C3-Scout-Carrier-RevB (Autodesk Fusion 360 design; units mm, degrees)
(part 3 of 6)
work_plane "WorkPlane4" AlongDistance -2.4 ExtraOffset 0
sketch "M3 nut outline" plane through (0, 0, -2.4) normal (0, 0, 1) x axis (1, 0, 0)
  line L1 (-10.41, -42.246) -> (-8.82, -45)
  line L2 (-13.59, -42.246) -> (-10.41, -42.246)
  line L3 (-15.18, -45) -> (-13.59, -42.246)
  line L4 (-13.59, -47.754) -> (-15.18, -45)
  line L5 (-10.41, -47.754) -> (-13.59, -47.754)
  line L6 (-8.82, -45) -> (-10.41, -47.754)
extrude "Extrude4" new body sketch "M3 nut outline" along normal blind 2.4
work_plane "WorkPlane5" AlongDistance -2.4 ExtraOffset 0
sketch "Nut thread clearance profile" plane through (0, 0, -2.4) normal (0, 0, 1) x axis (1, 0, 0)
  circle C1 centre (-12, -45) radius 1.55
extrude "Extrude5" cut sketch "Nut thread clearance profile" along normal blind 2.4
work_plane "WorkPlane6" AlongDistance -3.2 ExtraOffset 0
sketch "M3 x8 shank profile (1)" plane through (0, 0, -3.2) normal (0, 0, 1) x axis (1, 0, 0)
  circle C1 centre (12, -45) radius 1.5
extrude "Extrude6" new body sketch "M3 x8 shank profile (1)" along normal blind 8
work_plane "WorkPlane7" AlongDistance 4.8 ExtraOffset 0
sketch "M3 button head profile (1)" plane through (0, 0, 4.8) normal (0, 0, 1) x axis (1, 0, 0)
  circle C1 centre (12, -45) radius 2.7
extrude "Extrude7" new body sketch "M3 button head profile (1)" along normal blind 2.2
work_plane "WorkPlane8" AlongDistance 5.9 ExtraOffset 0
sketch "M3 hex drive (1)" plane through (0, 0, 5.9) normal (0, 0, 1) x axis (1, 0, 0)
  line L1 (12.7, -43.7876) -> (13.4, -45)
  line L2 (11.3, -43.7876) -> (12.7, -43.7876)
  line L3 (10.6, -45) -> (11.3, -43.7876)
  line L4 (11.3, -46.2124) -> (10.6, -45)
  line L5 (12.7, -46.2124) -> (11.3, -46.2124)
  line L6 (13.4, -45) -> (12.7, -46.2124)
extrude "Extrude8" cut sketch "M3 hex drive (1)" along normal blind 1.1
work_plane "WorkPlane9" AlongDistance -2.4 ExtraOffset 0
sketch "M3 nut outline (1)" plane through (0, 0, -2.4) normal (0, 0, 1) x axis (1, 0, 0)
  line L1 (13.59, -42.246) -> (15.18, -45)
  line L2 (10.41, -42.246) -> (13.59, -42.246)
  line L3 (8.82, -45) -> (10.41, -42.246)
  line L4 (10.41, -47.754) -> (8.82, -45)
  line L5 (13.59, -47.754) -> (10.41, -47.754)
  line L6 (15.18, -45) -> (13.59, -47.754)
extrude "Extrude9" new body sketch "M3 nut outline (1)" along normal blind 2.4
work_plane "WorkPlane10" AlongDistance -2.4 ExtraOffset 0
sketch "Nut thread clearance profile (1)" plane through (0, 0, -2.4) normal (0, 0, 1) x axis (1, 0, 0)
  circle C1 centre (12, -45) radius 1.55
extrude "Extrude10" cut sketch "Nut thread clearance profile (1)" along normal blind 2.4
sketch "Clear bumper lower beam profile" plane through (0, 0, 0) normal (0, 0, 1) x axis (1, 0, 0)
  line L1 (18, -52) -> (-18, -52)
  line L2 (18, -49.7) -> (18, -52)
  line L3 (-18, -49.7) -> (18, -49.7)
  line L4 (-18, -52) -> (-18, -49.7)
extrude "Extrude8" cut sketch "Clear bumper lower beam profile" along normal blind 1.8
work_plane "WorkPlane6" AlongDistance 3 ExtraOffset 0
sketch "PCB shoulder clearance behind USB mouth profile" plane through (0, 0, 3) normal (0, 0, 1) x axis (1, 0, 0)
  line L1 (9, -51.3) -> (-9, -51.3)
  line L2 (9, -49.5) -> (9, -51.3)
  line L3 (-9, -49.5) -> (9, -49.5)
  line L4 (-9, -51.3) -> (-9, -49.5)
extrude "Extrude10" cut sketch "PCB shoulder clearance behind USB mouth profile" along normal blind 3.2
work_plane "WorkPlane3" AlongDistance 4.8 ExtraOffset 0
sketch "Leave solder pads accessible profile" plane through (0, 0, 4.8) normal (0, 0, 1) x axis (1, 0, 0)
  line L1 (-4.4, -29.4) -> (-7, -29.4)
  line L2 (-4.4, -26.9) -> (-4.4, -29.4)
  line L3 (-7, -26.9) -> (-4.4, -26.9)
  line L4 (-7, -29.4) -> (-7, -26.9)
extrude "Extrude3" cut sketch "Leave solder pads accessible profile" along normal blind 1.3
work_plane "WorkPlane4" AlongDistance 4.8 ExtraOffset 0
sketch "Leave solder pads accessible profile (1)" plane through (0, 0, 4.8) normal (0, 0, 1) x axis (1, 0, 0)
  line L1 (7, -29.4) -> (4.4, -29.4)
  line L2 (7, -26.9) -> (7, -29.4)
  line L3 (4.4, -26.9) -> (7, -26.9)
  line L4 (4.4, -29.4) -> (4.4, -26.9)
extrude "Extrude4" cut sketch "Leave solder pads accessible profile (1)" along normal blind 1.3
sketch "Chamfered driver carrier outline" plane through (0, 0, 0) normal (0, 0, 1) x axis (1, 0, 0)
  line L1 (12.15, -13.5) -> (-12.15, -13.5)
  line L2 (14.15, -11.5) -> (12.15, -13.5)
  line L3 (14.15, 11.5) -> (14.15, -11.5)
  line L4 (12.15, 13.5) -> (14.15, 11.5)
  line L5 (-12.15, 13.5) -> (12.15, 13.5)
  line L6 (-14.15, 11.5) -> (-12.15, 13.5)
  line L7 (-14.15, -11.5) -> (-14.15, 11.5)
  line L8 (-12.15, -13.5) -> (-14.15, -11.5)
extrude "Extrude1" new body sketch "Chamfered driver carrier outline" along normal blind 1.6
sketch "Driver underside cooling opening profile" plane through (0, 0, 0) normal (0, 0, 1) x axis (1, 0, 0)
  line L1 (5, -3.5) -> (-5, -3.5)
  line L2 (5, 5) -> (5, -3.5)
  line L3 (-5, 5) -> (5, 5)
  line L4 (-5, -3.5) -> (-5, 5)
extrude "Extrude2" cut sketch "Driver underside cooling opening profile" along normal blind 1.6
work_plane "WorkPlane1" AlongDistance 1.6 ExtraOffset 0
sketch "End locating rail profile" plane through (0, 0, 1.6) normal (0, 0, 1) x axis (1, 0, 0)
  line L1 (8, -12.3) -> (-8, -12.3)
  line L2 (8, -10.8) -> (8, -12.3)
  line L3 (-8, -10.8) -> (8, -10.8)
  line L4 (-8, -12.3) -> (-8, -10.8)
extrude "Extrude3" add sketch "End locating rail profile" along normal blind 2.1
work_plane "WorkPlane2" AlongDistance 1.6 ExtraOffset 0
sketch "End locating rail profile (1)" plane through (0, 0, 1.6) normal (0, 0, 1) x axis (1, 0, 0)
  line L1 (8, 10.8) -> (-8, 10.8)
  line L2 (8, 12.3) -> (8, 10.8)
  line L3 (-8, 12.3) -> (8, 12.3)
  line L4 (-8, 10.8) -> (-8, 12.3)
extrude "Extrude4" add sketch "End locating rail profile (1)" along normal blind 2.1
work_plane "WorkPlane3" AlongDistance 1.6 ExtraOffset 0
sketch "Side locating tab profile" plane through (0, 0, 1.6) normal (0, 0, 1) x axis (1, 0, 0)
  line L1 (-12.65, -2) -> (-14.15, -2)
  line L2 (-12.65, 2) -> (-12.65, -2)
  line L3 (-14.15, 2) -> (-12.65, 2)
  line L4 (-14.15, -2) -> (-14.15, 2)
extrude "Extrude5" add sketch "Side locating tab profile" along normal blind 2.1
work_plane "WorkPlane4" AlongDistance 1.6 ExtraOffset 0
sketch "Side locating tab profile (1)" plane through (0, 0, 1.6) normal (0, 0, 1) x axis (1, 0, 0)
  line L1 (14.15, -2) -> (12.65, -2)
  line L2 (14.15, 2) -> (14.15, -2)
  line L3 (12.65, 2) -> (14.15, 2)
  line L4 (12.65, -2) -> (12.65, 2)
extrude "Extrude6" add sketch "Side locating tab profile (1)" along normal blind 2.1
sketch "Cable access profile" plane through (0, 0, 0) normal (0, 0, 1) x axis (1, 0, 0)
  line L1 (-11.5, 4) -> (-13.5, 4)
  line L2 (-11.5, 8) -> (-11.5, 4)
  line L3 (-13.5, 8) -> (-11.5, 8)
  line L4 (-13.5, 4) -> (-13.5, 8)
extrude "Extrude7" cut sketch "Cable access profile" along normal blind 1.6
sketch "Cable access profile (1)" plane through (0, 0, 0) normal (0, 0, 1) x axis (1, 0, 0)
  line L1 (13.5, 4) -> (11.5, 4)
  line L2 (13.5, 8) -> (13.5, 4)
  line L3 (11.5, 8) -> (13.5, 8)
  line L4 (11.5, 4) -> (11.5, 8)
extrude "Extrude8" cut sketch "Cable access profile (1)" along normal blind 1.6
sketch "Red PCB 24.7 x21 provisional profile" plane through (0, 0, 0) normal (0, 0, 1) x axis (1, 0, 0)
  line L1 (12.35, -10.5) -> (-12.35, -10.5)
  line L2 (12.35, 10.5) -> (12.35, -10.5)
  line L3 (-12.35, 10.5) -> (12.35, 10.5)
  line L4 (-12.35, -10.5) -> (-12.35, 10.5)
extrude "Extrude1" new body sketch "Red PCB 24.7 x21 provisional profile" along normal blind 1
sketch "Solder through holes profile" plane through (0, 0, 0) normal (0, 0, 1) x axis (1, 0, 0)
  circle C1 centre (-7.2, -0.3) radius 0.625
  circle C2 centre (-7.2, 2.24) radius 0.625
  circle C3 centre (-7.2, 5.8) radius 0.625
  circle C4 centre (-7.2, 8.34) radius 0.625
  circle C5 centre (7.8, -0.3) radius 0.625
  circle C6 centre (7.8, 2.24) radius 0.625
  circle C7 centre (7.8, 5.8) radius 0.625
  circle C8 centre (7.8, 8.34) radius 0.625
  circle C9 centre (-10.8, -8.8) radius 0.625
  circle C10 centre (-10.8, -5.6) radius 0.625
extrude "Extrude2" cut sketch "Solder through holes profile" along normal blind 1
sketch "Uncommitted mounting hole reference profile" plane through (0, 0, 0) normal (0, 0, 1) x axis (1, 0, 0)
  circle C1 centre (-10.4, -2.5) radius 1.15
extrude "Extrude3" cut sketch "Uncommitted mounting hole reference profile" along normal blind 1
work_plane "WorkPlane1" AlongDistance 1 ExtraOffset 0
sketch "Top solder pads profiles" plane through (0, 0, 1) normal (0, 0, 1) x axis (1, 0, 0)
  circle C1 centre (-7.2, -0.3) radius 1.25
  circle C2 centre (-7.2, -0.3) radius 0.625
  circle C3 centre (-7.2, 2.24) radius 1.25
  circle C4 centre (-7.2, 2.24) radius 0.625
  circle C5 centre (-7.2, 5.8) radius 1.25
  circle C6 centre (-7.2, 5.8) radius 0.625
  circle C7 centre (-7.2, 8.34) radius 1.25
  circle C8 centre (-7.2, 8.34) radius 0.625
  circle C9 centre (7.8, -0.3) radius 1.25
  circle C10 centre (7.8, -0.3) radius 0.625
  circle C11 centre (7.8, 2.24) radius 1.25
  circle C12 centre (7.8, 2.24) radius 0.625
  circle C13 centre (7.8, 5.8) radius 1.25
  circle C14 centre (7.8, 5.8) radius 0.625
  circle C15 centre (7.8, 8.34) radius 1.25
  circle C16 centre (7.8, 8.34) radius 0.625
  circle C17 centre (-10.8, -8.8) radius 1.25
  circle C18 centre (-10.8, -8.8) radius 0.625
  circle C19 centre (-10.8, -5.6) radius 1.25
  circle C20 centre (-10.8, -5.6) radius 0.625
extrude "Extrude4" new body sketch "Top solder pads profiles" along normal blind 0.04
work_plane "WorkPlane2" AlongDistance -0.04 ExtraOffset 0
sketch "Bottom solder pads profiles" plane through (0, 0, -0.04) normal (0, 0, 1) x axis (1, 0, 0)
  circle C1 centre (-7.2, -0.3) radius 1.25
  circle C2 centre (-7.2, -0.3) radius 0.625
  circle C3 centre (-7.2, 2.24) radius 1.25
  circle C4 centre (-7.2, 2.24) radius 0.625
  circle C5 centre (-7.2, 5.8) radius 1.25
  circle C6 centre (-7.2, 5.8) radius 0.625
  circle C7 centre (-7.2, 8.34) radius 1.25
  circle C8 centre (-7.2, 8.34) radius 0.625
  circle C9 centre (7.8, -0.3) radius 1.25
  circle C10 centre (7.8, -0.3) radius 0.625
  circle C11 centre (7.8, 2.24) radius 1.25
  circle C12 centre (7.8, 2.24) radius 0.625
  circle C13 centre (7.8, 5.8) radius 1.25
  circle C14 centre (7.8, 5.8) radius 0.625
  circle C15 centre (7.8, 8.34) radius 1.25
  circle C16 centre (7.8, 8.34) radius 0.625
  circle C17 centre (-10.8, -8.8) radius 1.25
  circle C18 centre (-10.8, -8.8) radius 0.625
  circle C19 centre (-10.8, -5.6) radius 1.25
  circle C20 centre (-10.8, -5.6) radius 0.625
extrude "Extrude5" new body sketch "Bottom solder pads profiles" along normal blind 0.04
work_plane "WorkPlane3" AlongDistance 1.2 ExtraOffset 0
sketch "TC1508A SOP16 body profile" plane through (0, 0, 1.2) normal (0, 0, 1) x axis (1, 0, 0)
  line L1 (1.95, -0.7) -> (-1.95, -0.7)
  line L2 (1.95, 9.2) -> (1.95, -0.7)
  line L3 (-1.95, 9.2) -> (1.95, 9.2)
  line L4 (-1.95, -0.7) -> (-1.95, 9.2)
extrude "Extrude6" new body sketch "TC1508A SOP16 body profile" along normal blind 1.5
work_plane "WorkPlane4" AlongDistance 1.04 ExtraOffset 0
sketch "Sixteen formed IC leads profiles" plane through (0, 0, 1.04) normal (0, 0, 1) x axis (1, 0, 0)
  line L1 (-1.8, -0.405) -> (-3.05, -0.405)
  line L2 (-1.8, 0.015) -> (-1.8, -0.405)
  line L3 (-3.05, 0.015) -> (-1.8, 0.015)
  line L4 (-3.05, -0.405) -> (-3.05, 0.015)
  line L5 (-1.8, 0.865) -> (-3.05, 0.865)
  line L6 (-1.8, 1.285) -> (-1.8, 0.865)
  line L7 (-3.05, 1.285) -> (-1.8, 1.285)
  line L8 (-3.05, 0.865) -> (-3.05, 1.285)
  line L9 (-1.8, 2.135) -> (-3.05, 2.135)
  line L10 (-1.8, 2.555) -> (-1.8, 2.135)
  line L11 (-3.05, 2.555) -> (-1.8, 2.555)
  line L12 (-3.05, 2.135) -> (-3.05, 2.555)
  line L13 (-1.8, 3.405) -> (-3.05, 3.405)
  line L14 (-1.8, 3.825) -> (-1.8, 3.405)
  line L15 (-3.05, 3.825) -> (-1.8, 3.825)
  line L16 (-3.05, 3.405) -> (-3.05, 3.825)
  line L17 (-1.8, 4.675) -> (-3.05, 4.675)
  line L18 (-1.8, 5.095) -> (-1.8, 4.675)
  line L19 (-3.05, 5.095) -> (-1.8, 5.095)
  line L20 (-3.05, 4.675) -> (-3.05, 5.095)
  line L21 (-1.8, 5.945) -> (-3.05, 5.945)
  line L22 (-1.8, 6.365) -> (-1.8, 5.945)
  line L23 (-3.05, 6.365) -> (-1.8, 6.365)
  line L24 (-3.05, 5.945) -> (-3.05, 6.365)
  line L25 (-1.8, 7.215) -> (-3.05, 7.215)
  line L26 (-1.8, 7.635) -> (-1.8, 7.215)
  line L27 (-3.05, 7.635) -> (-1.8, 7.635)
  line L28 (-3.05, 7.215) -> (-3.05, 7.635)
  line L29 (-1.8, 8.485) -> (-3.05, 8.485)
  line L30 (-1.8, 8.905) -> (-1.8, 8.485)
  line L31 (-3.05, 8.905) -> (-1.8, 8.905)
  line L32 (-3.05, 8.485) -> (-3.05, 8.905)
  line L33 (3.05, -0.405) -> (1.8, -0.405)
  line L34 (3.05, 0.015) -> (3.05, -0.405)
  line L35 (1.8, 0.015) -> (3.05, 0.015)
  line L36 (1.8, -0.405) -> (1.8, 0.015)
  line L37 (3.05, 0.865) -> (1.8, 0.865)
  line L38 (3.05, 1.285) -> (3.05, 0.865)
  line L39 (1.8, 1.285) -> (3.05, 1.285)
  line L40 (1.8, 0.865) -> (1.8, 1.285)
  line L41 (3.05, 2.135) -> (1.8, 2.135)
  line L42 (3.05, 2.555) -> (3.05, 2.135)
  line L43 (1.8, 2.555) -> (3.05, 2.555)
  line L44 (1.8, 2.135) -> (1.8, 2.555)
  line L45 (3.05, 3.405) -> (1.8, 3.405)
  line L46 (3.05, 3.825) -> (3.05, 3.405)
  line L47 (1.8, 3.825) -> (3.05, 3.825)
  line L48 (1.8, 3.405) -> (1.8, 3.825)
  line L49 (3.05, 4.675) -> (1.8, 4.675)
  line L50 (3.05, 5.095) -> (3.05, 4.675)
  line L51 (1.8, 5.095) -> (3.05, 5.095)
  line L52 (1.8, 4.675) -> (1.8, 5.095)
  line L53 (3.05, 5.945) -> (1.8, 5.945)
  line L54 (3.05, 6.365) -> (3.05, 5.945)
  line L55 (1.8, 6.365) -> (3.05, 6.365)
  line L56 (1.8, 5.945) -> (1.8, 6.365)
  line L57 (3.05, 7.215) -> (1.8, 7.215)
  line L58 (3.05, 7.635) -> (3.05, 7.215)
  line L59 (1.8, 7.635) -> (3.05, 7.635)
  line L60 (1.8, 7.215) -> (1.8, 7.635)
  line L61 (3.05, 8.485) -> (1.8, 8.485)
  line L62 (3.05, 8.905) -> (3.05, 8.485)
  line L63 (1.8, 8.905) -> (3.05, 8.905)
  line L64 (1.8, 8.485) -> (1.8, 8.905)
extrude "Extrude7" new body sketch "Sixteen formed IC leads profiles" along normal blind 0.43
work_plane "WorkPlane5" AlongDistance 2.55 ExtraOffset 0
sketch "IC orientation dimple profile" plane through (0, 0, 2.55) normal (0, 0, 1) x axis (1, 0, 0)
  circle C1 centre (-1.2, -0.05) radius 0.25
extrude "Extrude8" cut sketch "IC orientation dimple profile" along normal blind 0.15
work_plane "WorkPlane6" AlongDistance 2.7 ExtraOffset 0
sketch "TC1508A marking" plane through (0, 0, 2.7) normal (0, 0, 1) x axis (1, 0, 0)
  dimension "d730" = 0.7
  dimension "d731" = "'TC1508A'"
extrude "Extrude9" new body sketch "TC1508A marking" along normal blind 0.02
work_plane "WorkPlane7" AlongDistance 1 ExtraOffset 0
sketch "Capacitor square foot profile" plane through (0, 0, 1) normal (0, 0, 1) x axis (1, 0, 0)
  line L1 (-0.6, -10) -> (-7.4, -10)
  line L2 (-0.6, -3.2) -> (-0.6, -10)
  line L3 (-7.4, -3.2) -> (-0.6, -3.2)
  line L4 (-7.4, -10) -> (-7.4, -3.2)
extrude "Extrude10" new body sketch "Capacitor square foot profile" along normal blind 1
work_plane "WorkPlane8" AlongDistance 2 ExtraOffset 0
sketch "100uF capacitor aluminum can profile" plane through (0, 0, 2) normal (0, 0, 1) x axis (1, 0, 0)
  circle C1 centre (-4, -6.6) radius 3.15
extrude "Extrude11" new body sketch "100uF capacitor aluminum can profile" along normal blind 4.2
work_plane "WorkPlane9" AlongDistance 6.2 ExtraOffset 0
sketch "Capacitor polarity stripe profile" plane through (0, 0, 6.2) normal (0, 0, 1) x axis (1, 0, 0)
  line L1 (-5.8, -7.2) -> (-6.8, -7.2)
  line L2 (-5.8, -6) -> (-5.8, -7.2)
  line L3 (-6.8, -6) -> (-5.8, -6)
  line L4 (-6.8, -7.2) -> (-6.8, -6)
extrude "Extrude12" new body sketch "Capacitor polarity stripe profile" along normal blind 0.025
work_plane "WorkPlane10" AlongDistance 6.2 ExtraOffset 0
sketch "100 marking" plane through (0, 0, 6.2) normal (0, 0, 1) x axis (1, 0, 0)
  dimension "d748" = 0.85
  dimension "d749" = "'100'"
extrude "Extrude13" new body sketch "100 marking" along normal blind 0.025
work_plane "WorkPlane11" AlongDistance 1 ExtraOffset 0
sketch "Capacitor square foot profile (1)" plane through (0, 0, 1) normal (0, 0, 1) x axis (1, 0, 0)
  line L1 (7, -10) -> (0.2, -10)
  line L2 (7, -3.2) -> (7, -10)
  line L3 (0.2, -3.2) -> (7, -3.2)
  line L4 (0.2, -10) -> (0.2, -3.2)
extrude "Extrude14" new body sketch "Capacitor square foot profile (1)" along normal blind 1
work_plane "WorkPlane12" AlongDistance 2 ExtraOffset 0
sketch "100uF capacitor aluminum can profile (1)" plane through (0, 0, 2) normal (0, 0, 1) x axis (1, 0, 0)
  circle C1 centre (3.6, -6.6) radius 3.15
extrude "Extrude15" new body sketch "100uF capacitor aluminum can profile (1)" along normal blind 4.2
work_plane "WorkPlane13" AlongDistance 6.2 ExtraOffset 0
sketch "Capacitor polarity stripe profile (1)" plane through (0, 0, 6.2) normal (0, 0, 1) x axis (1, 0, 0)
  line L1 (1.8, -7.2) -> (0.8, -7.2)
  line L2 (1.8, -6) -> (1.8, -7.2)
  line L3 (0.8, -6) -> (1.8, -6)
  line L4 (0.8, -7.2) -> (0.8, -6)
extrude "Extrude16" new body sketch "Capacitor polarity stripe profile (1)" along normal blind 0.025
work_plane "WorkPlane14" AlongDistance 6.2 ExtraOffset 0
sketch "100 marking (1)" plane through (0, 0, 6.2) normal (0, 0, 1) x axis (1, 0, 0)
  dimension "d766" = 0.85
  dimension "d767" = "'100'"
extrude "Extrude17" new body sketch "100 marking (1)" along normal blind 0.025
work_plane "WorkPlane15" AlongDistance 1 ExtraOffset 0
sketch "LED and resistor metal ends profiles" plane through (0, 0, 1) normal (0, 0, 1) x axis (1, 0, 0)
  line L1 (10.2, -9.7) -> (8.2, -9.7)
  line L2 (10.2, -9.2) -> (10.2, -9.7)
  line L3 (8.2, -9.2) -> (10.2, -9.2)
  line L4 (8.2, -9.7) -> (8.2, -9.2)
  line L5 (10.2, -7.8) -> (8.2, -7.8)
  line L6 (10.2, -7.3) -> (10.2, -7.8)
  line L7 (8.2, -7.3) -> (10.2, -7.3)
  line L8 (8.2, -7.8) -> (8.2, -7.3)
  line L9 (10.2, -6.5) -> (8.2, -6.5)
  line L10 (10.2, -6.1) -> (10.2, -6.5)
  line L11 (8.2, -6.1) -> (10.2, -6.1)
  line L12 (8.2, -6.5) -> (8.2, -6.1)
  line L13 (10.2, -4.6) -> (8.2, -4.6)
  line L14 (10.2, -4.2) -> (10.2, -4.6)
  line L15 (8.2, -4.2) -> (10.2, -4.2)
  line L16 (8.2, -4.6) -> (8.2, -4.2)
extrude "Extrude18" new body sketch "LED and resistor metal ends profiles" along normal blind 0.2
work_plane "WorkPlane16" AlongDistance 1.2 ExtraOffset 0
sketch "Series resistor profiles" plane through (0, 0, 1.2) normal (0, 0, 1) x axis (1, 0, 0)
  line L1 (10.1, -9.2) -> (8.3, -9.2)
  line L2 (10.1, -7.8) -> (10.1, -9.2)
  line L3 (8.3, -7.8) -> (10.1, -7.8)
  line L4 (8.3, -9.2) -> (8.3, -7.8)
extrude "Extrude19" new body sketch "Series resistor profiles" along normal blind 0.5
work_plane "WorkPlane17" AlongDistance 1.2 ExtraOffset 0
sketch "Power LED profile" plane through (0, 0, 1.2) normal (0, 0, 1) x axis (1, 0, 0)
  line L1 (10.1, -6.1) -> (8.3, -6.1)
  line L2 (10.1, -4.6) -> (10.1, -6.1)
  line L3 (8.3, -4.6) -> (10.1, -4.6)
  line L4 (8.3, -6.1) -> (8.3, -4.6)
extrude "Extrude20" new body sketch "Power LED profile" along normal blind 0.5
work_plane "WorkPlane18" AlongDistance 1 ExtraOffset 0
sketch "IN1 marking" plane through (0, 0, 1) normal (0, 0, 1) x axis (1, 0, 0)
  dimension "d784" = 0.7
  dimension "d785" = "'IN1'"
extrude "Extrude21" new body sketch "IN1 marking" along normal blind 0.025
work_plane "WorkPlane19" AlongDistance 1 ExtraOffset 0
sketch "IN2 marking" plane through (0, 0, 1) normal (0, 0, 1) x axis (1, 0, 0)
  dimension "d790" = 0.7
  dimension "d791" = "'IN2'"
extrude "Extrude22" new body sketch "IN2 marking" along normal blind 0.025
work_plane "WorkPlane20" AlongDistance 1 ExtraOffset 0
sketch "IN3 marking" plane through (0, 0, 1) normal (0, 0, 1) x axis (1, 0, 0)
  dimension "d796" = 0.7
  dimension "d797" = "'IN3'"
extrude "Extrude23" new body sketch "IN3 marking" along normal blind 0.025
work_plane "WorkPlane21" AlongDistance 1 ExtraOffset 0
sketch "IN4 marking" plane through (0, 0, 1) normal (0, 0, 1) x axis (1, 0, 0)
  dimension "d802" = 0.7
  dimension "d803" = "'IN4'"
extrude "Extrude24" new body sketch "IN4 marking" along normal blind 0.025
work_plane "WorkPlane22" AlongDistance 1 ExtraOffset 0
sketch "A marking" plane through (0, 0, 1) normal (0, 0, 1) x axis (1, 0, 0)
  dimension "d808" = 1
extrude "Extrude25" new body sketch "A marking" along normal blind 0.025
work_plane "WorkPlane23" AlongDistance 1 ExtraOffset 0
sketch "B marking" plane through (0, 0, 1) normal (0, 0, 1) x axis (1, 0, 0)
  dimension "d814" = 1
extrude "Extrude26" new body sketch "B marking" along normal blind 0.025
work_plane "WorkPlane24" AlongDistance 1 ExtraOffset 0
sketch "+ marking" plane through (0, 0, 1) normal (0, 0, 1) x axis (1, 0, 0)
  dimension "d820" = 1
extrude "Extrude27" new body sketch "+ marking" along normal blind 0.025
work_plane "WorkPlane25" AlongDistance 1 ExtraOffset 0
sketch "- marking" plane through (0, 0, 1) normal (0, 0, 1) x axis (1, 0, 0)
  dimension "d826" = 1
extrude "Extrude28" new body sketch "- marking" along normal blind 0.025
work_plane "WorkPlane1" AlongDistance 4.5 ExtraOffset 0
sketch "Tray attachment tape profile" plane through (0, 0, 4.5) normal (0, 0, 1) x axis (1, 0, 0)
  line L1 (27.5, -14.3) -> (9.5, -14.3)
  line L2 (27.5, -12.3) -> (27.5, -14.3)
  line L3 (9.5, -12.3) -> (27.5, -12.3)
  line L4 (9.5, -14.3) -> (9.5, -12.3)
extrude "Extrude1" new body sketch "Tray attachment tape profile" along normal blind 0.2
work_plane "WorkPlane2" AlongDistance 4.5 ExtraOffset 0
sketch "Tray attachment tape profile (1)" plane through (0, 0, 4.5) normal (0, 0, 1) x axis (1, 0, 0)
  line L1 (27.5, 9.5) -> (9.5, 9.5)
  line L2 (27.5, 11.5) -> (27.5, 9.5)
  line L3 (9.5, 11.5) -> (27.5, 11.5)
  line L4 (9.5, 9.5) -> (9.5, 11.5)
extrude "Extrude2" new body sketch "Tray attachment tape profile (1)" along normal blind 0.2
work_plane "WorkPlane3" AlongDistance 6.3 ExtraOffset 0
sketch "Board insulating tape profile" plane through (0, 0, 6.3) normal (0, 0, 1) x axis (1, 0, 0)
  line L1 (22.5, -10.5) -> (14.5, -10.5)
  line L2 (22.5, -8.5) -> (22.5, -10.5)
  line L3 (14.5, -8.5) -> (22.5, -8.5)
  line L4 (14.5, -10.5) -> (14.5, -8.5)
extrude "Extrude3" new body sketch "Board insulating tape profile" along normal blind 1
work_plane "WorkPlane4" AlongDistance 6.3 ExtraOffset 0
sketch "Board insulating tape profile (1)" plane through (0, 0, 6.3) normal (0, 0, 1) x axis (1, 0, 0)
  line L1 (22.5, 6.8) -> (14.5, 6.8)
  line L2 (22.5, 8.8) -> (22.5, 6.8)
  line L3 (14.5, 8.8) -> (22.5, 8.8)
  line L4 (14.5, 6.8) -> (14.5, 8.8)
extrude "Extrude4" new body sketch "Board insulating tape profile (1)" along normal blind 1
work_plane "WorkPlane24" AlongDistance 4.5 ExtraOffset 0
sketch "Rear rail clearance for carrier bracket profile" plane through (0, 0, 4.5) normal (0, 0, 1) x axis (1, 0, 0)
  line L1 (34, 60) -> (27.5, 60)
  line L2 (34, 66) -> (34, 60)
  line L3 (27.5, 66) -> (34, 66)
  line L4 (27.5, 60) -> (27.5, 66)
extrude "Extrude44" cut sketch "Rear rail clearance for carrier bracket profile" along normal blind 4
sketch "Chamfered FR4 outline outline" plane through (0, 0, 0) normal (0, 0, 1) x axis (1, 0, 0)
  line L1 (30, 0) -> (2, 0)
  line L2 (32, 2) -> (30, 0)
  line L3 (32, 80) -> (32, 2)
  line L4 (30, 82) -> (32, 80)
  line L5 (2, 82) -> (30, 82)
  line L6 (0, 80) -> (2, 82)
  line L7 (0, 2) -> (0, 80)
  line L8 (2, 0) -> (0, 2)
extrude "Extrude1" new body sketch "Chamfered FR4 outline outline" along normal blind 1.6
sketch "Antenna clearance cutout outline" plane through (0, 0, 0) normal (0, 0, 1) x axis (1, 0, 0)
  line L1 (23, 56) -> (11, 56)
  line L2 (23, 63) -> (23, 56)
  line L3 (11, 63) -> (23, 63)
  line L4 (11, 56) -> (11, 63)
extrude "Extrude2" cut sketch "Antenna clearance cutout outline" along normal blind 1.6
sketch "M2 clearance mounting holes profile" plane through (0, 0, 0) normal (0, 0, 1) x axis (1, 0, 0)
  circle C1 centre (3, 3) radius 1.1
  circle C2 centre (29, 3) radius 1.1
  circle C3 centre (3, 79) radius 1.1
  circle C4 centre (29, 79) radius 1.1
extrude "Extrude3" cut sketch "M2 clearance mounting holes profile" along normal blind 1.6
sketch "Plated holes 0.8 profile" plane through (0, 0, 0) normal (0, 0, 1) x axis (1, 0, 0)
  circle C1 centre (25.75, 16) radius 0.4
  circle C2 centre (28.25, 16) radius 0.4
extrude "Extrude4" cut sketch "Plated holes 0.8 profile" along normal blind 1.6
sketch "Plated holes 1.05 profile" plane through (0, 0, 0) normal (0, 0, 1) x axis (1, 0, 0)
  circle C1 centre (9.38, 77.14) radius 0.525
  circle C2 centre (9.38, 74.6) radius 0.525
  circle C3 centre (9.38, 72.06) radius 0.525
  circle C4 centre (9.38, 69.52) radius 0.525
  circle C5 centre (9.38, 66.98) radius 0.525
  circle C6 centre (9.38, 64.44) radius 0.525
  circle C7 centre (9.38, 61.9) radius 0.525
  circle C8 centre (9.38, 59.36) radius 0.525
  circle C9 centre (24.62, 77.14) radius 0.525
  circle C10 centre (24.62, 74.6) radius 0.525
  circle C11 centre (24.62, 72.06) radius 0.525
  circle C12 centre (24.62, 69.52) radius 0.525
  circle C13 centre (24.62, 66.98) radius 0.525
  circle C14 centre (24.62, 64.44) radius 0.525
  circle C15 centre (24.62, 61.9) radius 0.525
  circle C16 centre (24.62, 59.36) radius 0.525
extrude "Extrude5" cut sketch "Plated holes 1.05 profile" along normal blind 1.6
sketch "Plated holes 1.2 profile" plane through (0, 0, 0) normal (0, 0, 1) x axis (1, 0, 0)
  circle C1 centre (4, 17.25) radius 0.6
  circle C2 centre (4, 20.75) radius 0.6
  circle C3 centre (5, 7.25) radius 0.6
  circle C4 centre (5, 10.75) radius 0.6
  circle C5 centre (28, 7.25) radius 0.6
  circle C6 centre (28, 10.75) radius 0.6
  circle C7 centre (4, 47.25) radius 0.6
  circle C8 centre (4, 50.75) radius 0.6
extrude "Extrude6" cut sketch "Plated holes 1.2 profile" along normal blind 1.6
sketch "Plated holes 1.35 profile" plane through (0, 0, 0) normal (0, 0, 1) x axis (1, 0, 0)
  circle C1 centre (25.6, 19.68) radius 0.675
  circle C2 centre (29.4, 19.68) radius 0.675
  circle C3 centre (25.6, 28.32) radius 0.675
  circle C4 centre (29.4, 28.32) radius 0.675
extrude "Extrude7" cut sketch "Plated holes 1.35 profile" along normal blind 1.6
work_plane "WorkPlane1" AlongDistance 1.6 ExtraOffset 0
sketch "Exposed component pads profiles" plane through (0, 0, 1.6) normal (0, 0, 1) x axis (1, 0, 0)
  line L1 (14.15, 14.145) -> (12.45, 14.145)
  line L2 (14.15, 14.745) -> (14.15, 14.145)
  line L3 (12.45, 14.745) -> (14.15, 14.745)
  line L4 (12.45, 14.145) -> (12.45, 14.745)
  line L5 (19.55, 14.145) -> (17.85, 14.145)
  line L6 (19.55, 14.745) -> (19.55, 14.145)
  line L7 (17.85, 14.745) -> (19.55, 14.745)
  line L8 (17.85, 14.145) -> (17.85, 14.745)
  line L9 (14.15, 12.875) -> (12.45, 12.875)
  line L10 (14.15, 13.475) -> (14.15, 12.875)
  line L11 (12.45, 13.475) -> (14.15, 13.475)
  line L12 (12.45, 12.875) -> (12.45, 13.475)
  line L13 (19.55, 12.875) -> (17.85, 12.875)
  line L14 (19.55, 13.475) -> (19.55, 12.875)
  line L15 (17.85, 13.475) -> (19.55, 13.475)
  line L16 (17.85, 12.875) -> (17.85, 13.475)
  line L17 (14.15, 11.605) -> (12.45, 11.605)
  line L18 (14.15, 12.205) -> (14.15, 11.605)
  line L19 (12.45, 12.205) -> (14.15, 12.205)
  line L20 (12.45, 11.605) -> (12.45, 12.205)
  line L21 (19.55, 11.605) -> (17.85, 11.605)
  line L22 (19.55, 12.205) -> (19.55, 11.605)
  line L23 (17.85, 12.205) -> (19.55, 12.205)
  line L24 (17.85, 11.605) -> (17.85, 12.205)
  line L25 (14.15, 10.335) -> (12.45, 10.335)
  line L26 (14.15, 10.935) -> (14.15, 10.335)
  line L27 (12.45, 10.935) -> (14.15, 10.935)
  line L28 (12.45, 10.335) -> (12.45, 10.935)
  line L29 (19.55, 10.335) -> (17.85, 10.335)
  line L30 (19.55, 10.935) -> (19.55, 10.335)
  line L31 (17.85, 10.935) -> (19.55, 10.935)
  line L32 (17.85, 10.335) -> (17.85, 10.935)
  line L33 (14.15, 9.065) -> (12.45, 9.065)
  line L34 (14.15, 9.665) -> (14.15, 9.065)
  line L35 (12.45, 9.665) -> (14.15, 9.665)
  line L36 (12.45, 9.065) -> (12.45, 9.665)
  line L37 (19.55, 9.065) -> (17.85, 9.065)
  line L38 (19.55, 9.665) -> (19.55, 9.065)
  line L39 (17.85, 9.665) -> (19.55, 9.665)
  line L40 (17.85, 9.065) -> (17.85, 9.665)
  line L41 (14.15, 7.795) -> (12.45, 7.795)
  line L42 (14.15, 8.395) -> (14.15, 7.795)
  line L43 (12.45, 8.395) -> (14.15, 8.395)
  line L44 (12.45, 7.795) -> (12.45, 8.395)
  line L45 (19.55, 7.795) -> (17.85, 7.795)
  line L46 (19.55, 8.395) -> (19.55, 7.795)
  line L47 (17.85, 8.395) -> (19.55, 8.395)
  line L48 (17.85, 7.795) -> (17.85, 8.395)
  line L49 (14.15, 6.525) -> (12.45, 6.525)
  line L50 (14.15, 7.125) -> (14.15, 6.525)
  line L51 (12.45, 7.125) -> (14.15, 7.125)
  line L52 (12.45, 6.525) -> (12.45, 7.125)
  line L53 (19.55, 6.525) -> (17.85, 6.525)
  line L54 (19.55, 7.125) -> (19.55, 6.525)
  line L55 (17.85, 7.125) -> (19.55, 7.125)
  line L56 (17.85, 6.525) -> (17.85, 7.125)
  line L57 (14.15, 5.255) -> (12.45, 5.255)
  line L58 (14.15, 5.855) -> (14.15, 5.255)
  line L59 (12.45, 5.855) -> (14.15, 5.855)
  line L60 (12.45, 5.255) -> (12.45, 5.855)
  line L61 (19.55, 5.255) -> (17.85, 5.255)
  line L62 (19.55, 5.855) -> (19.55, 5.255)
  line L63 (17.85, 5.855) -> (19.55, 5.855)
  line L64 (17.85, 5.255) -> (17.85, 5.855)
  line L65 (9.15, 25.605) -> (7.45, 25.605)
  line L66 (9.15, 26.205) -> (9.15, 25.605)
  line L67 (7.45, 26.205) -> (9.15, 26.205)
  line L68 (7.45, 25.605) -> (7.45, 26.205)
  line L69 (14.55, 25.605) -> (12.85, 25.605)
  line L70 (14.55, 26.205) -> (14.55, 25.605)
  line L71 (12.85, 26.205) -> (14.55, 26.205)
  line L72 (12.85, 25.605) -> (12.85, 26.205)
  line L73 (9.15, 24.335) -> (7.45, 24.335)
  line L74 (9.15, 24.935) -> (9.15, 24.335)
  line L75 (7.45, 24.935) -> (9.15, 24.935)
  line L76 (7.45, 24.335) -> (7.45, 24.935)
  line L77 (14.55, 24.335) -> (12.85, 24.335)
  line L78 (14.55, 24.935) -> (14.55, 24.335)
  line L79 (12.85, 24.935) -> (14.55, 24.935)
  line L80 (12.85, 24.335) -> (12.85, 24.935)
  line L81 (9.15, 23.065) -> (7.45, 23.065)
  line L82 (9.15, 23.665) -> (9.15, 23.065)
  line L83 (7.45, 23.665) -> (9.15, 23.665)
  line L84 (7.45, 23.065) -> (7.45, 23.665)
  line L85 (14.55, 23.065) -> (12.85, 23.065)
  line L86 (14.55, 23.665) -> (14.55, 23.065)
  line L87 (12.85, 23.665) -> (14.55, 23.665)
  line L88 (12.85, 23.065) -> (12.85, 23.665)
  line L89 (9.15, 21.795) -> (7.45, 21.795)
  line L90 (9.15, 22.395) -> (9.15, 21.795)
  line L91 (7.45, 22.395) -> (9.15, 22.395)
  line L92 (7.45, 21.795) -> (7.45, 22.395)
  line L93 (14.55, 21.795) -> (12.85, 21.795)
  line L94 (14.55, 22.395) -> (14.55, 21.795)
  line L95 (12.85, 22.395) -> (14.55, 22.395)
  line L96 (12.85, 21.795) -> (12.85, 22.395)
  line L97 (12.125, 22.25) -> (9.875, 22.25)
  line L98 (12.125, 25.75) -> (12.125, 22.25)
  line L99 (9.875, 25.75) -> (12.125, 25.75)
  line L100 (9.875, 22.25) -> (9.875, 25.75)
  line L101 (4.875, 36.65) -> (3.825, 36.65)
  line L102 (4.875, 37.25) -> (4.875, 36.65)
  line L103 (3.825, 37.25) -> (4.875, 37.25)
  line L104 (3.825, 36.65) -> (3.825, 37.25)
  line L105 (7.175, 36.65) -> (6.125, 36.65)
  line L106 (7.175, 37.25) -> (7.175, 36.65)
  line L107 (6.125, 37.25) -> (7.175, 37.25)
  line L108 (6.125, 36.65) -> (6.125, 37.25)
  line L109 (4.875, 35.7) -> (3.825, 35.7)
  line L110 (4.875, 36.3) -> (4.875, 35.7)
  line L111 (3.825, 36.3) -> (4.875, 36.3)
  line L112 (3.825, 35.7) -> (3.825, 36.3)
  line L113 (7.175, 35.7) -> (6.125, 35.7)
  line L114 (7.175, 36.3) -> (7.175, 35.7)
  line L115 (6.125, 36.3) -> (7.175, 36.3)
  line L116 (6.125, 35.7) -> (6.125, 36.3)
  line L117 (4.875, 34.75) -> (3.825, 34.75)
  line L118 (4.875, 35.35) -> (4.875, 34.75)
  line L119 (3.825, 35.35) -> (4.875, 35.35)
  line L120 (3.825, 34.75) -> (3.825, 35.35)
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extrude "Extrude8" new body sketch "Exposed component pads profiles" along normal blind 0.035
work_plane "WorkPlane2" AlongDistance 1.6 ExtraOffset 0
sketch "Top plated annuli 0.95 profiles" plane through (0, 0, 1.6) normal (0, 0, 1) x axis (1, 0, 0)
  circle C1 centre (9.38, 77.14) radius 0.95
  circle C2 centre (9.38, 77.14) radius 0.525
  circle C3 centre (9.38, 74.6) radius 0.95
  circle C4 centre (9.38, 74.6) radius 0.525
  circle C5 centre (9.38, 72.06) radius 0.95
  circle C6 centre (9.38, 72.06) radius 0.525
  circle C7 centre (9.38, 69.52) radius 0.95
  circle C8 centre (9.38, 69.52) radius 0.525
  circle C9 centre (9.38, 66.98) radius 0.95
  circle C10 centre (9.38, 66.98) radius 0.525
  circle C11 centre (9.38, 64.44) radius 0.95
  circle C12 centre (9.38, 64.44) radius 0.525
  circle C13 centre (9.38, 61.9) radius 0.95
  circle C14 centre (9.38, 61.9) radius 0.525
  circle C15 centre (9.38, 59.36) radius 0.95
  circle C16 centre (9.38, 59.36) radius 0.525
  circle C17 centre (24.62, 77.14) radius 0.95
  circle C18 centre (24.62, 77.14) radius 0.525
  circle C19 centre (24.62, 74.6) radius 0.95
  circle C20 centre (24.62, 74.6) radius 0.525
  circle C21 centre (24.62, 72.06) radius 0.95
  circle C22 centre (24.62, 72.06) radius 0.525
  circle C23 centre (24.62, 69.52) radius 0.95
  circle C24 centre (24.62, 69.52) radius 0.525
  circle C25 centre (24.62, 66.98) radius 0.95
  circle C26 centre (24.62, 66.98) radius 0.525
  circle C27 centre (24.62, 64.44) radius 0.95
  circle C28 centre (24.62, 64.44) radius 0.525
  circle C29 centre (24.62, 61.9) radius 0.95
  circle C30 centre (24.62, 61.9) radius 0.525
  circle C31 centre (24.62, 59.36) radius 0.95
  circle C32 centre (24.62, 59.36) radius 0.525
extrude "Extrude9" new body sketch "Top plated annuli 0.95 profiles" along normal blind 0.035
work_plane "WorkPlane3" AlongDistance -0.035 ExtraOffset 0
sketch "Bottom plated annuli 0.95 profiles" plane through (0, 0, -0.035) normal (0, 0, 1) x axis (1, 0, 0)
  circle C1 centre (9.38, 77.14) radius 0.95
  circle C2 centre (9.38, 77.14) radius 0.525
  circle C3 centre (9.38, 74.6) radius 0.95
  circle C4 centre (9.38, 74.6) radius 0.525
  circle C5 centre (9.38, 72.06) radius 0.95
  circle C6 centre (9.38, 72.06) radius 0.525
  circle C7 centre (9.38, 69.52) radius 0.95
  circle C8 centre (9.38, 69.52) radius 0.525
  circle C9 centre (9.38, 66.98) radius 0.95
  circle C10 centre (9.38, 66.98) radius 0.525
  circle C11 centre (9.38, 64.44) radius 0.95
  circle C12 centre (9.38, 64.44) radius 0.525
  circle C13 centre (9.38, 61.9) radius 0.95
  circle C14 centre (9.38, 61.9) radius 0.525
  circle C15 centre (9.38, 59.36) radius 0.95
  circle C16 centre (9.38, 59.36) radius 0.525
  circle C17 centre (24.62, 77.14) radius 0.95
  circle C18 centre (24.62, 77.14) radius 0.525
  circle C19 centre (24.62, 74.6) radius 0.95
  circle C20 centre (24.62, 74.6) radius 0.525
  circle C21 centre (24.62, 72.06) radius 0.95
  circle C22 centre (24.62, 72.06) radius 0.525
  circle C23 centre (24.62, 69.52) radius 0.95
  circle C24 centre (24.62, 69.52) radius 0.525
  circle C25 centre (24.62, 66.98) radius 0.95
  circle C26 centre (24.62, 66.98) radius 0.525
  circle C27 centre (24.62, 64.44) radius 0.95
  circle C28 centre (24.62, 64.44) radius 0.525
  circle C29 centre (24.62, 61.9) radius 0.95
  circle C30 centre (24.62, 61.9) radius 0.525
  circle C31 centre (24.62, 59.36) radius 0.95
  circle C32 centre (24.62, 59.36) radius 0.525
extrude "Extrude10" new body sketch "Bottom plated annuli 0.95 profiles" along normal blind 0.035
work_plane "WorkPlane4" AlongDistance 1.6 ExtraOffset 0
sketch "Top plated annuli 1.1 profiles" plane through (0, 0, 1.6) normal (0, 0, 1) x axis (1, 0, 0)
  circle C1 centre (4, 17.25) radius 1.1
  circle C2 centre (4, 17.25) radius 0.6
  circle C3 centre (4, 20.75) radius 1.1
  circle C4 centre (4, 20.75) radius 0.6
  circle C5 centre (5, 7.25) radius 1.1
  circle C6 centre (5, 7.25) radius 0.6
  circle C7 centre (5, 10.75) radius 1.1
  circle C8 centre (5, 10.75) radius 0.6
  circle C9 centre (28, 7.25) radius 1.1
  circle C10 centre (28, 7.25) radius 0.6
  circle C11 centre (28, 10.75) radius 1.1
  circle C12 centre (28, 10.75) radius 0.6
  circle C13 centre (4, 47.25) radius 1.1
  circle C14 centre (4, 47.25) radius 0.6
  circle C15 centre (4, 50.75) radius 1.1
  circle C16 centre (4, 50.75) radius 0.6
extrude "Extrude11" new body sketch "Top plated annuli 1.1 profiles" along normal blind 0.035
work_plane "WorkPlane5" AlongDistance -0.035 ExtraOffset 0
sketch "Bottom plated annuli 1.1 profiles" plane through (0, 0, -0.035) normal (0, 0, 1) x axis (1, 0, 0)
  circle C1 centre (4, 17.25) radius 1.1
  circle C2 centre (4, 17.25) radius 0.6
  circle C3 centre (4, 20.75) radius 1.1
  circle C4 centre (4, 20.75) radius 0.6
  circle C5 centre (5, 7.25) radius 1.1
  circle C6 centre (5, 7.25) radius 0.6
  circle C7 centre (5, 10.75) radius 1.1
  circle C8 centre (5, 10.75) radius 0.6
  circle C9 centre (28, 7.25) radius 1.1
  circle C10 centre (28, 7.25) radius 0.6
  circle C11 centre (28, 10.75) radius 1.1
  circle C12 centre (28, 10.75) radius 0.6
  circle C13 centre (4, 47.25) radius 1.1
  circle C14 centre (4, 47.25) radius 0.6
  circle C15 centre (4, 50.75) radius 1.1
  circle C16 centre (4, 50.75) radius 0.6
extrude "Extrude12" new body sketch "Bottom plated annuli 1.1 profiles" along normal blind 0.035
work_plane "WorkPlane6" AlongDistance 1.6 ExtraOffset 0
sketch "Top plated annuli 1.0 profiles" plane through (0, 0, 1.6) normal (0, 0, 1) x axis (1, 0, 0)
  circle C1 centre (25.6, 19.68) radius 1
  circle C2 centre (25.6, 19.68) radius 0.675
  circle C3 centre (29.4, 19.68) radius 1
  circle C4 centre (29.4, 19.68) radius 0.675
  circle C5 centre (25.6, 28.32) radius 1
  circle C6 centre (25.6, 28.32) radius 0.675
  circle C7 centre (29.4, 28.32) radius 1
  circle C8 centre (29.4, 28.32) radius 0.675
extrude "Extrude13" new body sketch "Top plated annuli 1.0 profiles" along normal blind 0.035
work_plane "WorkPlane7" AlongDistance -0.035 ExtraOffset 0
sketch "Bottom plated annuli 1.0 profiles" plane through (0, 0, -0.035) normal (0, 0, 1) x axis (1, 0, 0)
  circle C1 centre (25.6, 19.68) radius 1
  circle C2 centre (25.6, 19.68) radius 0.675
  circle C3 centre (29.4, 19.68) radius 1
  circle C4 centre (29.4, 19.68) radius 0.675
  circle C5 centre (25.6, 28.32) radius 1
  circle C6 centre (25.6, 28.32) radius 0.675
  circle C7 centre (29.4, 28.32) radius 1
  circle C8 centre (29.4, 28.32) radius 0.675
extrude "Extrude14" new body sketch "Bottom plated annuli 1.0 profiles" along normal blind 0.035
work_plane "WorkPlane8" AlongDistance 1.6 ExtraOffset 0
sketch "Top plated annuli 0.9 profiles" plane through (0, 0, 1.6) normal (0, 0, 1) x axis (1, 0, 0)
  circle C1 centre (25.75, 16) radius 0.9
  circle C2 centre (25.75, 16) radius 0.4
  circle C3 centre (28.25, 16) radius 0.9
  circle C4 centre (28.25, 16) radius 0.4
extrude "Extrude15" new body sketch "Top plated annuli 0.9 profiles" along normal blind 0.035
work_plane "WorkPlane9" AlongDistance -0.035 ExtraOffset 0
sketch "Bottom plated annuli 0.9 profiles" plane through (0, 0, -0.035) normal (0, 0, 1) x axis (1, 0, 0)
  circle C1 centre (25.75, 16) radius 0.9
  circle C2 centre (25.75, 16) radius 0.4
  circle C3 centre (28.25, 16) radius 0.9
  circle C4 centre (28.25, 16) radius 0.4
extrude "Extrude16" new body sketch "Bottom plated annuli 0.9 profiles" along normal blind 0.035
work_plane "WorkPlane10" AlongDistance 1.64 ExtraOffset 0
sketch "SCOUT A marking" plane through (0, 0, 1.64) normal (0, 0, 1) x axis (1, 0, 0)
  dimension "d902" = 1.5
extrude "Extrude17" new body sketch "SCOUT A marking" along normal blind 0.015
work_plane "WorkPlane11" AlongDistance 1.64 ExtraOffset 0
sketch "500mA marking" plane through (0, 0, 1.64) normal (0, 0, 1) x axis (1, 0, 0)
  dimension "d908" = 1.05
  dimension "d909" = "'500mA'"
extrude "Extrude18" new body sketch "500mA marking" along normal blind 0.015
work_plane "WorkPlane12" AlongDistance 1.64 ExtraOffset 0
sketch "RUN OFF marking" plane through (0, 0, 1.64) normal (0, 0, 1) x axis (1, 0, 0)
  dimension "d914" = 1
extrude "Extrude19" new body sketch "RUN OFF marking" along normal blind 0.015
work_plane "WorkPlane1" AlongDistance 0.2 ExtraOffset 0
sketch "Molded package profile" plane through (0, 0, 0.2) normal (0, 0, 1) x axis (1, 0, 0)
  line L1 (1.95, -4.95) -> (-1.95, -4.95)
  line L2 (1.95, 4.95) -> (1.95, -4.95)
  line L3 (-1.95, 4.95) -> (1.95, 4.95)
  line L4 (-1.95, -4.95) -> (-1.95, 4.95)
extrude "Extrude1" new body sketch "Molded package profile" along normal blind 1.1
sketch "Lead solder feet profiles" plane through (0, 0, 0) normal (0, 0, 1) x axis (1, 0, 0)
  line L1 (-2.7, 4.205) -> (-3.55, 4.205)
  line L2 (-2.7, 4.685) -> (-2.7, 4.205)
  line L3 (-3.55, 4.685) -> (-2.7, 4.685)
  line L4 (-3.55, 4.205) -> (-3.55, 4.685)
  line L5 (3.55, 4.205) -> (2.7, 4.205)
  line L6 (3.55, 4.685) -> (3.55, 4.205)
  line L7 (2.7, 4.685) -> (3.55, 4.685)
  line L8 (2.7, 4.205) -> (2.7, 4.685)
  line L9 (-2.7, 2.935) -> (-3.55, 2.935)
  line L10 (-2.7, 3.415) -> (-2.7, 2.935)
  line L11 (-3.55, 3.415) -> (-2.7, 3.415)
  line L12 (-3.55, 2.935) -> (-3.55, 3.415)
  line L13 (3.55, 2.935) -> (2.7, 2.935)
  line L14 (3.55, 3.415) -> (3.55, 2.935)
  line L15 (2.7, 3.415) -> (3.55, 3.415)
  line L16 (2.7, 2.935) -> (2.7, 3.415)
  line L17 (-2.7, 1.665) -> (-3.55, 1.665)
  line L18 (-2.7, 2.145) -> (-2.7, 1.665)
  line L19 (-3.55, 2.145) -> (-2.7, 2.145)
  line L20 (-3.55, 1.665) -> (-3.55, 2.145)
  line L21 (3.55, 1.665) -> (2.7, 1.665)
  line L22 (3.55, 2.145) -> (3.55, 1.665)
  line L23 (2.7, 2.145) -> (3.55, 2.145)
  line L24 (2.7, 1.665) -> (2.7, 2.145)
  line L25 (-2.7, 0.395) -> (-3.55, 0.395)
  line L26 (-2.7, 0.875) -> (-2.7, 0.395)
  line L27 (-3.55, 0.875) -> (-2.7, 0.875)
  line L28 (-3.55, 0.395) -> (-3.55, 0.875)
  line L29 (3.55, 0.395) -> (2.7, 0.395)
  line L30 (3.55, 0.875) -> (3.55, 0.395)
  line L31 (2.7, 0.875) -> (3.55, 0.875)
  line L32 (2.7, 0.395) -> (2.7, 0.875)
  line L33 (-2.7, -0.875) -> (-3.55, -0.875)
  line L34 (-2.7, -0.395) -> (-2.7, -0.875)
  line L35 (-3.55, -0.395) -> (-2.7, -0.395)
  line L36 (-3.55, -0.875) -> (-3.55, -0.395)
  line L37 (3.55, -0.875) -> (2.7, -0.875)
  line L38 (3.55, -0.395) -> (3.55, -0.875)
  line L39 (2.7, -0.395) -> (3.55, -0.395)
  line L40 (2.7, -0.875) -> (2.7, -0.395)
  line L41 (-2.7, -2.145) -> (-3.55, -2.145)
  line L42 (-2.7, -1.665) -> (-2.7, -2.145)
  line L43 (-3.55, -1.665) -> (-2.7, -1.665)
  line L44 (-3.55, -2.145) -> (-3.55, -1.665)
  line L45 (3.55, -2.145) -> (2.7, -2.145)
  line L46 (3.55, -1.665) -> (3.55, -2.145)
  line L47 (2.7, -1.665) -> (3.55, -1.665)
  line L48 (2.7, -2.145) -> (2.7, -1.665)
  line L49 (-2.7, -3.415) -> (-3.55, -3.415)
  line L50 (-2.7, -2.935) -> (-2.7, -3.415)
  line L51 (-3.55, -2.935) -> (-2.7, -2.935)
  line L52 (-3.55, -3.415) -> (-3.55, -2.935)
  line L53 (3.55, -3.415) -> (2.7, -3.415)
  line L54 (3.55, -2.935) -> (3.55, -3.415)
  line L55 (2.7, -2.935) -> (3.55, -2.935)
  line L56 (2.7, -3.415) -> (2.7, -2.935)
  line L57 (-2.7, -4.685) -> (-3.55, -4.685)
  line L58 (-2.7, -4.205) -> (-2.7, -4.685)
  line L59 (-3.55, -4.205) -> (-2.7, -4.205)
  line L60 (-3.55, -4.685) -> (-3.55, -4.205)
  line L61 (3.55, -4.685) -> (2.7, -4.685)
  line L62 (3.55, -4.205) -> (3.55, -4.685)
  line L63 (2.7, -4.205) -> (3.55, -4.205)
  line L64 (2.7, -4.685) -> (2.7, -4.205)
extrude "Extrude2" new body sketch "Lead solder feet profiles" along normal blind 0.15
work_plane "WorkPlane2" AlongDistance 0.1 ExtraOffset 0
sketch "Formed lead risers profiles" plane through (0, 0, 0.1) normal (0, 0, 1) x axis (1, 0, 0)
  line L1 (-2.12, 4.205) -> (-2.78, 4.205)
  line L2 (-2.12, 4.685) -> (-2.12, 4.205)
  line L3 (-2.78, 4.685) -> (-2.12, 4.685)
  line L4 (-2.78, 4.205) -> (-2.78, 4.685)
  line L5 (2.78, 4.205) -> (2.12, 4.205)
  line L6 (2.78, 4.685) -> (2.78, 4.205)
  line L7 (2.12, 4.685) -> (2.78, 4.685)
  line L8 (2.12, 4.205) -> (2.12, 4.685)
  line L9 (-2.12, 2.935) -> (-2.78, 2.935)
  line L10 (-2.12, 3.415) -> (-2.12, 2.935)
  line L11 (-2.78, 3.415) -> (-2.12, 3.415)
  line L12 (-2.78, 2.935) -> (-2.78, 3.415)
  line L13 (2.78, 2.935) -> (2.12, 2.935)
  line L14 (2.78, 3.415) -> (2.78, 2.935)
  line L15 (2.12, 3.415) -> (2.78, 3.415)
  line L16 (2.12, 2.935) -> (2.12, 3.415)
  line L17 (-2.12, 1.665) -> (-2.78, 1.665)
  line L18 (-2.12, 2.145) -> (-2.12, 1.665)
  line L19 (-2.78, 2.145) -> (-2.12, 2.145)
  line L20 (-2.78, 1.665) -> (-2.78, 2.145)
  line L21 (2.78, 1.665) -> (2.12, 1.665)
  line L22 (2.78, 2.145) -> (2.78, 1.665)
  line L23 (2.12, 2.145) -> (2.78, 2.145)
  line L24 (2.12, 1.665) -> (2.12, 2.145)
  line L25 (-2.12, 0.395) -> (-2.78, 0.395)
  line L26 (-2.12, 0.875) -> (-2.12, 0.395)
  line L27 (-2.78, 0.875) -> (-2.12, 0.875)
  line L28 (-2.78, 0.395) -> (-2.78, 0.875)
  line L29 (2.78, 0.395) -> (2.12, 0.395)
  line L30 (2.78, 0.875) -> (2.78, 0.395)
  line L31 (2.12, 0.875) -> (2.78, 0.875)
  line L32 (2.12, 0.395) -> (2.12, 0.875)
  line L33 (-2.12, -0.875) -> (-2.78, -0.875)
  line L34 (-2.12, -0.395) -> (-2.12, -0.875)
  line L35 (-2.78, -0.395) -> (-2.12, -0.395)
  line L36 (-2.78, -0.875) -> (-2.78, -0.395)
  line L37 (2.78, -0.875) -> (2.12, -0.875)
  line L38 (2.78, -0.395) -> (2.78, -0.875)
  line L39 (2.12, -0.395) -> (2.78, -0.395)
  line L40 (2.12, -0.875) -> (2.12, -0.395)
  line L41 (-2.12, -2.145) -> (-2.78, -2.145)
  line L42 (-2.12, -1.665) -> (-2.12, -2.145)
  line L43 (-2.78, -1.665) -> (-2.12, -1.665)
  line L44 (-2.78, -2.145) -> (-2.78, -1.665)
  line L45 (2.78, -2.145) -> (2.12, -2.145)
  line L46 (2.78, -1.665) -> (2.78, -2.145)
  line L47 (2.12, -1.665) -> (2.78, -1.665)
  line L48 (2.12, -2.145) -> (2.12, -1.665)
  line L49 (-2.12, -3.415) -> (-2.78, -3.415)
  line L50 (-2.12, -2.935) -> (-2.12, -3.415)
  line L51 (-2.78, -2.935) -> (-2.12, -2.935)
  line L52 (-2.78, -3.415) -> (-2.78, -2.935)
  line L53 (2.78, -3.415) -> (2.12, -3.415)
  line L54 (2.78, -2.935) -> (2.78, -3.415)
  line L55 (2.12, -2.935) -> (2.78, -2.935)
  line L56 (2.12, -3.415) -> (2.12, -2.935)
  line L57 (-2.12, -4.685) -> (-2.78, -4.685)
  line L58 (-2.12, -4.205) -> (-2.12, -4.685)
  line L59 (-2.78, -4.205) -> (-2.12, -4.205)
  line L60 (-2.78, -4.685) -> (-2.78, -4.205)
  line L61 (2.78, -4.685) -> (2.12, -4.685)
  line L62 (2.78, -4.205) -> (2.78, -4.685)
  line L63 (2.12, -4.205) -> (2.78, -4.205)
  line L64 (2.12, -4.685) -> (2.12, -4.205)
extrude "Extrude3" new body sketch "Formed lead risers profiles" along normal blind 0.45
work_plane "WorkPlane3" AlongDistance 0.45 ExtraOffset 0
sketch "Lead shoulders profiles" plane through (0, 0, 0.45) normal (0, 0, 1) x axis (1, 0, 0)
  line L1 (-1.95, 4.205) -> (-2.2, 4.205)
  line L2 (-1.95, 4.685) -> (-1.95, 4.205)
  line L3 (-2.2, 4.685) -> (-1.95, 4.685)
  line L4 (-2.2, 4.205) -> (-2.2, 4.685)
  line L5 (2.2, 4.205) -> (1.95, 4.205)
  line L6 (2.2, 4.685) -> (2.2, 4.205)
  line L7 (1.95, 4.685) -> (2.2, 4.685)
  line L8 (1.95, 4.205) -> (1.95, 4.685)
  line L9 (-1.95, 2.935) -> (-2.2, 2.935)
  line L10 (-1.95, 3.415) -> (-1.95, 2.935)
  line L11 (-2.2, 3.415) -> (-1.95, 3.415)
  line L12 (-2.2, 2.935) -> (-2.2, 3.415)
  line L13 (2.2, 2.935) -> (1.95, 2.935)
  line L14 (2.2, 3.415) -> (2.2, 2.935)
  line L15 (1.95, 3.415) -> (2.2, 3.415)
  line L16 (1.95, 2.935) -> (1.95, 3.415)
  line L17 (-1.95, 1.665) -> (-2.2, 1.665)
  line L18 (-1.95, 2.145) -> (-1.95, 1.665)
  line L19 (-2.2, 2.145) -> (-1.95, 2.145)
  line L20 (-2.2, 1.665) -> (-2.2, 2.145)
  line L21 (2.2, 1.665) -> (1.95, 1.665)
  line L22 (2.2, 2.145) -> (2.2, 1.665)
  line L23 (1.95, 2.145) -> (2.2, 2.145)
  line L24 (1.95, 1.665) -> (1.95, 2.145)
  line L25 (-1.95, 0.395) -> (-2.2, 0.395)
  line L26 (-1.95, 0.875) -> (-1.95, 0.395)
  line L27 (-2.2, 0.875) -> (-1.95, 0.875)
  line L28 (-2.2, 0.395) -> (-2.2, 0.875)
  line L29 (2.2, 0.395) -> (1.95, 0.395)
  line L30 (2.2, 0.875) -> (2.2, 0.395)
  line L31 (1.95, 0.875) -> (2.2, 0.875)
  line L32 (1.95, 0.395) -> (1.95, 0.875)
  line L33 (-1.95, -0.875) -> (-2.2, -0.875)
  line L34 (-1.95, -0.395) -> (-1.95, -0.875)
  line L35 (-2.2, -0.395) -> (-1.95, -0.395)
  line L36 (-2.2, -0.875) -> (-2.2, -0.395)
  line L37 (2.2, -0.875) -> (1.95, -0.875)
  line L38 (2.2, -0.395) -> (2.2, -0.875)
  line L39 (1.95, -0.395) -> (2.2, -0.395)
  line L40 (1.95, -0.875) -> (1.95, -0.395)
  line L41 (-1.95, -2.145) -> (-2.2, -2.145)
  line L42 (-1.95, -1.665) -> (-1.95, -2.145)
  line L43 (-2.2, -1.665) -> (-1.95, -1.665)
  line L44 (-2.2, -2.145) -> (-2.2, -1.665)
  line L45 (2.2, -2.145) -> (1.95, -2.145)
  line L46 (2.2, -1.665) -> (2.2, -2.145)
  line L47 (1.95, -1.665) -> (2.2, -1.665)
  line L48 (1.95, -2.145) -> (1.95, -1.665)
  line L49 (-1.95, -3.415) -> (-2.2, -3.415)
  line L50 (-1.95, -2.935) -> (-1.95, -3.415)
  line L51 (-2.2, -2.935) -> (-1.95, -2.935)
  line L52 (-2.2, -3.415) -> (-2.2, -2.935)
  line L53 (2.2, -3.415) -> (1.95, -3.415)
  line L54 (2.2, -2.935) -> (2.2, -3.415)
  line L55 (1.95, -2.935) -> (2.2, -2.935)
  line L56 (1.95, -3.415) -> (1.95, -2.935)
  line L57 (-1.95, -4.685) -> (-2.2, -4.685)
  line L58 (-1.95, -4.205) -> (-1.95, -4.685)
  line L59 (-2.2, -4.205) -> (-1.95, -4.205)
  line L60 (-2.2, -4.685) -> (-2.2, -4.205)
  line L61 (2.2, -4.685) -> (1.95, -4.685)
  line L62 (2.2, -4.205) -> (2.2, -4.685)
  line L63 (1.95, -4.205) -> (2.2, -4.205)
  line L64 (1.95, -4.685) -> (1.95, -4.205)
extrude "Extrude4" new body sketch "Lead shoulders profiles" along normal blind 0.15
work_plane "WorkPlane4" AlongDistance 1.3 ExtraOffset 0
sketch "Pin 1 indicator profile" plane through (0, 0, 1.3) normal (0, 0, 1) x axis (1, 0, 0)
  circle C1 centre (-1.4, 4.4) radius 0.18
extrude "Extrude5" new body sketch "Pin 1 indicator profile" along normal blind 0.015
work_plane "WorkPlane5" AlongDistance 1.3 ExtraOffset 0
sketch "1508A marking" plane through (0, 0, 1.3) normal (0, 0, 1) x axis (1, 0, 0)
  dimension "d938" = 0.7
  dimension "d939" = "'1508A'"
extrude "Extrude6" new body sketch "1508A marking" along normal blind 0.012
work_plane "WorkPlane1" AlongDistance 0.2 ExtraOffset 0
